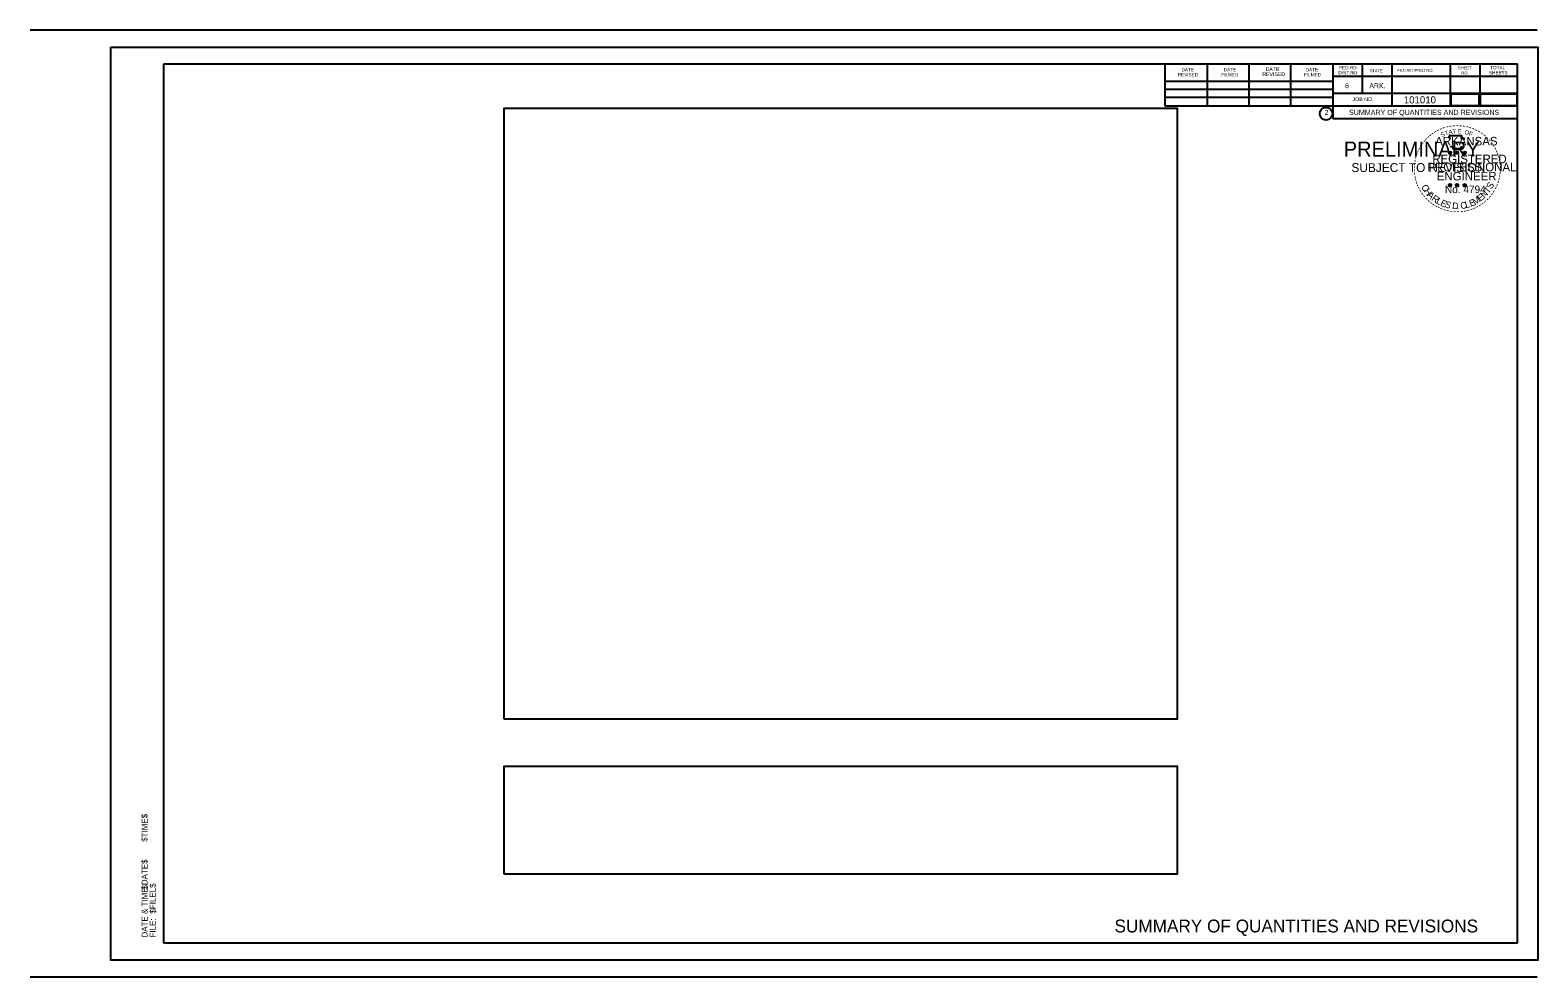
# Model space of a CAD drawing. Extents: x 9844 to 18514, y 8651 to 12569.
# Drawn here: x 16754 to 18514, y 9961 to 11067 of the extents above; entities that cross this region are included whole.
import ezdxf

# ---------------------------------------------------------------- set-up
doc = ezdxf.new("R2010")
doc.units = 0
for name, color, linetype in [('Default', 7, 'Continuous'), ('Quantities', 7, 'Continuous'), ('R_Border Notes', 7, 'Continuous'), ('R_No Plot', 7, 'Continuous'), ('STAMP_PE_CRAFTON-SIGNATURE', 7, 'Continuous'), ('STAMP_PE_SEAL-INFO', 7, 'Continuous'), ('STAMP_PE_TXT', 7, 'Continuous'), ('STAMP_PRELIMINARY', 7, 'Continuous'), ('Total_Pages', 7, 'Continuous')]:
    doc.layers.add(name, color=color, linetype=linetype)

msp = doc.modelspace()

# ---------------------------------------------------------------- linework, layer by layer
at = {"layer": 'Quantities'}
for points in [[(17306.7, 10262.2), (18093.7, 10262.2), (18093.7, 10975.2), (17306.7, 10975.2)], [(17306.7, 10080.8), (18093.7, 10080.8), (18093.7, 10206.3), (17306.7, 10206.3)]]:
    msp.add_lwpolyline(points, close=True, dxfattribs=at)
at = {"layer": 'R_No Plot'}
msp.add_lwpolyline([(18412.6, 10978.6), (18446, 10978.6), (18446, 10991.9), (18412.6, 10991.9)], close=True, dxfattribs=at)
at = {"layer": 'STAMP_PE_SEAL-INFO'}
msp.add_lwpolyline([(16847.7, 11046.8), (18514.4, 11046.8), (18514.4, 9980.1), (16847.7, 9980.1)], close=True, dxfattribs=at)
at = {"layer": 'STAMP_PE_TXT'}
for p, q in [((18410, 10924), (18411.8, 10923.5)), ((18410, 10924), (18411.3, 10923.8)), ((18410, 10924), (18411.2, 10923.4)), ((18410.7, 10922), (18411.8, 10923.5)), ((18410.7, 10922), (18411.3, 10923.2)), ((18410.7, 10922), (18411.8, 10923.1)), ((18411.8, 10925.3), (18411.6, 10924.1)), ((18411.8, 10923.5), (18411.8, 10925.3)), ((18411.8, 10925.3), (18412, 10924.1)), ((18413.5, 10924), (18411.8, 10923.5)), ((18412.9, 10922), (18411.8, 10923.5)), ((18412.9, 10922), (18411.8, 10923.1)), ((18413.5, 10924), (18412.1, 10923.8)), ((18412.9, 10922), (18412.2, 10923.5)), ((18413.5, 10924), (18412.5, 10923.5)), ((18418.4, 10924), (18420.1, 10923.5)), ((18418.4, 10924), (18419.7, 10923.8)), ((18418.4, 10924), (18419.6, 10923.4)), ((18419.1, 10922), (18420.1, 10923.5)), ((18419.1, 10922), (18419.7, 10923.2)), ((18419.1, 10922), (18420.1, 10923.1)), ((18420.1, 10925.3), (18419.9, 10924.1)), ((18420.1, 10923.5), (18420.1, 10925.3)), ((18420.1, 10925.3), (18420.4, 10924.1)), ((18421.9, 10924), (18420.1, 10923.5)), ((18421.2, 10922), (18420.1, 10923.5)), ((18421.2, 10922), (18420.1, 10923.1)), ((18421.9, 10924), (18420.4, 10923.8)), ((18421.2, 10922), (18420.5, 10923.5)), ((18421.9, 10924), (18420.9, 10923.5)), ((18427.2, 10924), (18429, 10923.4)), ((18427.2, 10924), (18428.5, 10923.8)), ((18427.2, 10924), (18428.4, 10923.4)), ((18427.9, 10921.9), (18429, 10923.4)), ((18427.9, 10921.9), (18428.5, 10923.2)), ((18427.9, 10921.9), (18429, 10923)), ((18429, 10925.3), (18428.8, 10924)), ((18429, 10923.4), (18429, 10925.3)), ((18429, 10925.3), (18429.2, 10924)), ((18430.7, 10924), (18429, 10923.4)), ((18430, 10921.9), (18429, 10923.4)), ((18430, 10921.9), (18429, 10923)), ((18430.7, 10924), (18429.3, 10923.7)), ((18430, 10921.9), (18429.3, 10923.4)), ((18430.7, 10924), (18429.7, 10923.5)), ((18410, 10886.2), (18411.8, 10885.6)), ((18410, 10886.2), (18411.3, 10886)), ((18410, 10886.2), (18411.2, 10885.6)), ((18410.7, 10884.1), (18411.8, 10885.6)), ((18410.7, 10884.1), (18411.3, 10885.4)), ((18410.7, 10884.1), (18411.8, 10885.2)), ((18411.8, 10887.4), (18411.6, 10886.2)), ((18411.8, 10885.6), (18411.8, 10887.4)), ((18411.8, 10887.4), (18412, 10886.2)), ((18413.5, 10886.2), (18411.8, 10885.6)), ((18412.8, 10884.1), (18411.8, 10885.6)), ((18412.8, 10884.1), (18411.8, 10885.2)), ((18413.5, 10886.2), (18412.1, 10885.9)), ((18412.8, 10884.1), (18412.2, 10885.6)), ((18413.5, 10886.2), (18412.5, 10885.7)), ((18418.4, 10886.2), (18420.1, 10885.6)), ((18418.4, 10886.2), (18419.6, 10886)), ((18418.4, 10886.2), (18419.6, 10885.6)), ((18419, 10884.1), (18420.1, 10885.6)), ((18419, 10884.1), (18419.7, 10885.4)), ((18419, 10884.1), (18420.1, 10885.2)), ((18420.1, 10887.4), (18419.9, 10886.2)), ((18420.1, 10885.6), (18420.1, 10887.4)), ((18420.1, 10887.4), (18420.4, 10886.2)), ((18421.9, 10886.2), (18420.1, 10885.6)), ((18421.2, 10884.1), (18420.1, 10885.6)), ((18421.2, 10884.1), (18420.1, 10885.2)), ((18421.9, 10886.2), (18420.4, 10885.9)), ((18421.2, 10884.1), (18420.5, 10885.6)), ((18421.9, 10886.2), (18420.8, 10885.7)), ((18427.2, 10886.1), (18429, 10885.6)), ((18427.2, 10886.1), (18428.5, 10885.9)), ((18427.2, 10886.1), (18428.4, 10885.5)), ((18427.9, 10884.1), (18429, 10885.6)), ((18427.9, 10884.1), (18428.5, 10885.3)), ((18427.9, 10884.1), (18428.9, 10885.2)), ((18429, 10887.4), (18428.7, 10886.1)), ((18430, 10884.1), (18428.9, 10885.2)), ((18429, 10885.6), (18429, 10887.4)), ((18429, 10887.4), (18429.2, 10886.1)), ((18430.7, 10886.1), (18429, 10885.6)), ((18430, 10884.1), (18429, 10885.6)), ((18430.7, 10886.1), (18429.3, 10885.9)), ((18430, 10884.1), (18429.3, 10885.5)), ((18430.7, 10886.1), (18429.7, 10885.6))]:
    msp.add_line(p, q, dxfattribs=at)
for points in [[(18410.3, 10943.4), (18411.6, 10939.3)], [(18427.8, 10938.8), (18428.5, 10940.2), (18425.1, 10940.1), (18425.8, 10943.4), (18410.3, 10943.4)], [(18411.8, 10925.3), (18412.9, 10922), (18410, 10924), (18413.5, 10924), (18410.7, 10922), (18411.8, 10925.3)], [(18412.7, 10931.3), (18412.7, 10930.9), (18415.5, 10930.8), (18415.3, 10928.4), (18424.6, 10928.4), (18425.6, 10931.1)], [(18420.1, 10925.3), (18421.2, 10922), (18418.4, 10924), (18421.9, 10924), (18419.1, 10922), (18420.1, 10925.3)], [(18429, 10925.3), (18430, 10921.9), (18427.2, 10924), (18430.7, 10924), (18427.9, 10921.9), (18429, 10925.3)], [(18411.8, 10887.4), (18412.8, 10884.1), (18410, 10886.2), (18413.5, 10886.2), (18410.7, 10884.1), (18411.8, 10887.4)], [(18420.1, 10887.4), (18421.2, 10884.1), (18418.4, 10886.2), (18421.9, 10886.2), (18419, 10884.1), (18420.1, 10887.4)], [(18429, 10887.4), (18430, 10884.1), (18427.2, 10886.1), (18430.7, 10886.1), (18427.9, 10884.1), (18429, 10887.4)]]:
    msp.add_lwpolyline(points, dxfattribs=at)
for centre, radius in [((18411.8, 10923.5), 0.861), ((18411.8, 10923.5), 0.723), ((18411.8, 10923.5), 0.579), ((18411.8, 10923.5), 0.495), ((18411.8, 10923.5), 0.374), ((18411.8, 10923.5), 0.248), ((18411.8, 10923.5), 0.148), ((18420.1, 10923.5), 0.861), ((18420.1, 10923.5), 0.723), ((18420.1, 10923.5), 0.579), ((18420.1, 10923.5), 0.495), ((18420.1, 10923.5), 0.374), ((18420.1, 10923.5), 0.248), ((18420.1, 10923.5), 0.148), ((18429, 10923.4), 0.861), ((18429, 10923.4), 0.723), ((18429, 10923.4), 0.579), ((18429, 10923.4), 0.495), ((18429, 10923.4), 0.374), ((18429, 10923.4), 0.248), ((18429, 10923.4), 0.148), ((18411.8, 10885.6), 0.861), ((18411.8, 10885.6), 0.723), ((18411.8, 10885.6), 0.579), ((18411.8, 10885.6), 0.495), ((18411.8, 10885.6), 0.374), ((18411.8, 10885.6), 0.248), ((18411.8, 10885.6), 0.148), ((18420.1, 10885.6), 0.861), ((18420.1, 10885.6), 0.723), ((18420.1, 10885.6), 0.579), ((18420.1, 10885.6), 0.495), ((18420.1, 10885.6), 0.374), ((18420.1, 10885.6), 0.248), ((18420.1, 10885.6), 0.148), ((18428.9, 10885.6), 0.861), ((18428.9, 10885.6), 0.723), ((18428.9, 10885.6), 0.579), ((18428.9, 10885.6), 0.495), ((18428.9, 10885.6), 0.374), ((18428.9, 10885.6), 0.248), ((18428.9, 10885.6), 0.148)]:
    msp.add_circle(centre, radius, dxfattribs=at)
at = {"layer": 'STAMP_PRELIMINARY'}
for p, q in [((18513.6, 11066.7), (16753.6, 11066.7)), ((16909.7, 11027.3), (18490.6, 11027.3)), ((16909.7, 10000), (16909.7, 11027.3)), ((17672.3, 11026), (17672.3, 11026)), ((17672.3, 11026), (17672.3, 11026)), ((18079.3, 10977.9), (18079.3, 11027.3)), ((18128.6, 10977.9), (18128.6, 11026.3)), ((18177.4, 10977.9), (18177.4, 11026.3)), ((18225.8, 10977.9), (18225.8, 11026.3)), ((18275.1, 11027.3), (18275.1, 10963.3)), ((18309.3, 11027.3), (18309.3, 10992.6)), ((18344, 11027.3), (18344, 10977.9)), ((18411.9, 11027.3), (18411.9, 10977.9)), ((18446.6, 11027.3), (18446.6, 10977.9)), ((18490.6, 10000), (18490.6, 11027.3)), ((18079.3, 11007.2), (18275.1, 11007.2)), ((18490.6, 11012.6), (18275.1, 11012.6)), ((18490.6, 11012.7), (18490.6, 11012.7)), ((18079.3, 10997.9), (18275.1, 10997.9)), ((18079.3, 10988.2), (18275.1, 10988.2)), ((18490.6, 10992.6), (18275.1, 10992.6)), ((18490.6, 10977.9), (18079.3, 10977.9)), ((18275.1, 10963.3), (18490.6, 10963.3)), ((18490.6, 10000), (16909.7, 10000)), ((16753.6, 9960.6), (18513.6, 9960.6))]:
    msp.add_line(p, q, dxfattribs=at)
msp.add_circle((18267.1, 10969), 7.33, dxfattribs=at)
at = {"layer": 'Total_Pages'}
msp.add_lwpolyline([(18447.1, 10978.6), (18490.2, 10978.6), (18490.2, 10991.9), (18447.1, 10991.9)], close=True, dxfattribs=at)

# ---------------------------------------------------------------- texts
at = {"layer": 'Default'}
for s, height, p in [('$TIME$', 6.98, (16890.7, 10118.4)), ('$DATE$', 6.98, (16890.7, 10062.5)), ('DATE & TIME:', 6.984, (16890.7, 10006.6)), ('$FILEL$', 6.98, (16900.3, 10034.5)), ('FILE: ', 6.98, (16900.3, 10006.6))]:
    msp.add_text(s, height=height, rotation=90, dxfattribs=at).set_placement(p)
at = {"layer": 'R_Border Notes'}
for s, height, p in [('101010', 8.4, (18357.9, 10981.1)), ('SUMMARY OF QUANTITIES AND REVISIONS', 6, (18293.9, 10967.6))]:
    msp.add_text(s, height=height, dxfattribs=at).set_placement(p)
at = {"layer": 'STAMP_PE_CRAFTON-SIGNATURE'}
for s, height, p in [('PRELIMINARY', 17.5, (18287.7, 10919)), ('SUBJECT TO REVISION', 10.376, (18296.7, 10900.9))]:
    msp.add_text(s, height=height, dxfattribs=at).set_placement(p)
at = {"layer": 'STAMP_PE_TXT'}
for s, height, rotation, p in [('-', 8, 24.3072, (18400.8, 10947.7)), ('-', 8, 19.1761, (18404, 10949.1)), ('-', 8, 13.6302, (18407.7, 10950.3)), ('-', 8, 10.2193, (18411.1, 10951.1)), ('-', 8, 5.8968, (18414.8, 10951.6)), ('-', 8, 0.1862, (18418.6, 10952)), ('-', 8, 357.743, (18422.3, 10951.9)), ('-', 8, 352.1617, (18426, 10951.6)), ('-', 8, 347.2049, (18429.6, 10951.1)), ('-', 8, 342.3362, (18432.7, 10950.3)), ('-', 8, 337.8551, (18436.4, 10949.2)), ('-', 8, 54.2325, (18380.9, 10930.7)), ('-', 8, 50.6142, (18383, 10933.5)), ('-', 8, 48.4231, (18385, 10935.9)), ('-', 8, 42.9622, (18387.2, 10938.3)), ('-', 8, 38.9507, (18389.4, 10940.4)), ('-', 8, 36.2317, (18391.8, 10942.3)), ('-', 8, 34.0636, (18394.7, 10944.3)), ('-', 8, 28.7918, (18397.7, 10946.1)), ('S', 5, 21.594, (18402, 10941.8)), ('T', 5, 16.4036, (18406.6, 10943.5)), ('A', 5, 11.2132, (18410.7, 10944.7)), ('T', 5, 6.0228, (18415, 10945.6)), ('E', 5, 0.8323, (18420.5, 10946.1)), ('O', 5, 350.4515, (18428.5, 10945.1)), ('F', 5, 340.0707, (18433.3, 10943.9)), ('-', 8, 334.1211, (18439.6, 10947.8)), ('-', 8, 329.6409, (18442.5, 10946.4)), ('-', 8, 325.8627, (18445.7, 10944.6)), ('-', 8, 320.5297, (18448.7, 10942.5)), ('-', 8, 315.5786, (18451.7, 10940)), ('-', 8, 309.8797, (18454.6, 10937.3)), ('-', 8, 306.6522, (18457.2, 10934.3)), ('-', 8, 75.461, (18374.4, 10915.2)), ('-', 8, 72.3945, (18375.3, 10918.8)), ('-', 8, 67.7743, (18376.4, 10921.9)), ('-', 8, 62.8713, (18377.7, 10925)), ('-', 8, 58.0706, (18379.3, 10928)), ('-', 7, 303.6753, (18459.6, 10931.4)), ('-', 8, 299.6684, (18461.2, 10928.4)), ('-', 8, 294.6628, (18462.8, 10925.3)), ('-', 8, 290.5728, (18464.1, 10922.5)), ('-', 8, 285.1233, (18465.3, 10919.6)), ('-', 8, 94.1959, (18373.4, 10901.1)), ('-', 8, 89.0622, (18373.2, 10904.7)), ('-', 8, 98.9479, (18373.7, 10897.7)), ('-', 8, 85.1863, (18373.3, 10908.2)), ('-', 8, 81.2013, (18373.7, 10911.6)), ('-', 8, 280.5493, (18466.3, 10915.9)), ('-', 8, 276.5962, (18467.1, 10912)), ('-', 8, 263.5172, (18467.5, 10901.9)), ('-', 8, 274.3301, (18467.4, 10908.4)), ('-', 8, 269.9407, (18467.6, 10905.2)), ('-', 8, 101.7149, (18374.4, 10894.1)), ('-', 8, 105.4578, (18375.2, 10891.1)), ('-', 8, 109.0874, (18376.3, 10887.9)), ('-', 8, 114.0643, (18377.6, 10884.9)), ('-', 8, 115.7289, (18379.1, 10881.9)), ('C', 7.7, 296.9133, (18377.9, 10883.9)), ('H', 7.7, 303.2799, (18380.9, 10878.7)), ('T', 7.7, 51.5114, (18456.6, 10875.1)), ('S', 7.7, 57.878, (18460.2, 10880.3)), ('-', 8, 244.6197, (18463.2, 10885.1)), ('-', 8, 247.8887, (18464.6, 10888.3)), ('-', 8, 255.7626, (18465.6, 10891.8)), ('-', 8, 255.7626, (18466.6, 10895.3)), ('-', 8, 260.9953, (18467.1, 10898.6)), ('-', 8, 120.4471, (18380.9, 10878.9)), ('-', 8, 125.8934, (18382.9, 10876.1)), ('-', 8, 130.7181, (18385.2, 10873.4)), ('-', 8, 134.2238, (18387.8, 10870.6)), ('A', 7.7, 316.013, (18384.5, 10873.6)), ('-', 8, 138.9338, (18390.4, 10868.3)), ('-', 8, 144.6463, (18393.2, 10866.3)), ('R', 7.7, 322.3796, (18389.6, 10868.7)), ('L', 7.7, 328.7461, (18394.8, 10864.9)), ('E', 7.7, 335.1127, (18399.8, 10862.1)), ('S', 7.7, 341.4792, (18405.1, 10860)), ('D', 7.7, 354.2124, (18414, 10857.9)), ('C', 7.7, 6.9455, (18424.4, 10857.7)), ('L', 7.7, 13.3121, (18430.3, 10858.7)), ('E', 7.7, 19.6786, (18435.8, 10860.3)), ('M', 7.7, 32.4117, (18440.9, 10862.1)), ('E', 7.7, 38.7783, (18447.3, 10866.2)), ('N', 7.7, 45.1449, (18451.8, 10869.9)), ('-', 8, 215.7363, (18449.4, 10867.6)), ('-', 8, 221.0851, (18452.1, 10869.9)), ('-', 8, 225.7653, (18454.7, 10872.5)), ('-', 8, 231.2538, (18457.1, 10875.3)), ('-', 8, 233.8452, (18459.3, 10878.1)), ('-', 8, 239.0712, (18461.3, 10881.4)), ('-', 8, 148.0898, (18396, 10864.4)), ('-', 8, 151.5704, (18398.9, 10862.8)), ('-', 8, 154.6002, (18401.5, 10861.6)), ('-', 8, 158.5612, (18404.6, 10860.3)), ('-', 8, 162.7983, (18408, 10859.2)), ('-', 8, 167.5555, (18411.6, 10858.4)), ('-', 8, 173.1155, (18415.5, 10857.9)), ('-', 8, 176.5183, (18419.2, 10857.6)), ('-', 8, 181.5918, (18422.9, 10857.7)), ('.', 7.7, 0.5789, (18419.8, 10857.5)), ('-', 8, 185.8167, (18427, 10858.1)), ('-', 8, 191.2858, (18430.7, 10858.7)), ('-', 8, 195.4743, (18434.3, 10859.7)), ('-', 8, 200.7184, (18437.7, 10860.9)), ('-', 8, 204.2516, (18440.8, 10862.3)), ('-', 8, 207.3568, (18443.9, 10863.9)), ('-', 8, 212.2491, (18446.7, 10865.6))]:
    msp.add_text(s, height=height, rotation=rotation, dxfattribs=at).set_placement(p)
for s, height, p in [('ARKANSAS', 10, (18394.5, 10932)), ('REGISTERED', 10, (18391.1, 10911.2)), ('PROFESSIONAL', 10, (18385.4, 10901.7)), ('ENGINEER', 10, (18396.3, 10891.1)), ('No. 4794', 8.78, (18405.9, 10876.3))]:
    msp.add_text(s, height=height, dxfattribs=at).set_placement(p)
at = {"layer": 'STAMP_PRELIMINARY'}
for s, height, p in [('DATE', 3.91, (18098.3, 11018.5)), ('DATE', 3.91, (18147.6, 11018.5)), ('DATE', 4.4, (18196.5, 11019)), ('DATE', 3.91, (18243.4, 11018.5)), ('FED.RD.', 3.91, (18282.5, 11020.9)), ('SHEET', 3.42, (18421.2, 11020.9)), ('TOTAL', 3.91, (18458.8, 11020.9)), ('REVISED', 3.91, (18093.9, 11012.6)), ('FILMED', 3.91, (18144.7, 11012.6)), ('REVISED', 4.4, (18192.6, 11013.1)), ('FILMED', 3.91, (18241.4, 11012.6)), ('DIST.NO.', 3.91, (18281.5, 11015)), ('6', 5.86, (18289.3, 10998.9)), ('STATE', 3.42, (18318.1, 11017.5)), ('FED.AID PROJ.NO.', 3.42, (18350.4, 11018)), ('NO.', 3.42, (18425.1, 11015)), ('SHEETS', 3.91, (18457.4, 11015)), ('JOB NO.', 4.4, (18298.1, 10983.8)), ('ARK.', 5.86, (18317.6, 10998.9)), ('2', 5.86, (18265.4, 10967.7)), ('SUMMARY OF QUANTITIES AND REVISIONS', 15, (18020, 10012.5))]:
    msp.add_text(s, height=height, dxfattribs=at).set_placement(p)

doc.saveas('drawing.dxf')
